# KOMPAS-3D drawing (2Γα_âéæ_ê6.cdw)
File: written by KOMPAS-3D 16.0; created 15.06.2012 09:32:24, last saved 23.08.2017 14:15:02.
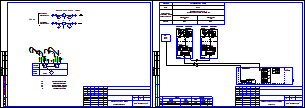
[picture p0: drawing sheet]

Sheets 1-2: A3, landscape

Title block, sheet 1: name: Руководство по эксплуатации; sheet number: 1; sheets: 27; organisation: ООО"Интелприбор"; sheet format: A3; stored path: W:\Users\smirnov_v\Desktop\шаблоны\4-х трубка\4-х трубка ГВС-max.cdw / D:\Проекты\Лыткарино\ул. Квартал 3А, д.25\710.74 РП.cdw; file name: 4-х трубка ГВС-max.cdw / 710.74 РП.cdw; cell 51: МО, Воскресенсикй р-н, п. Хорлово, ул. Интернациональная, д. 4; cell 320: Р
Title block, sheet 2: sheet number: 2

Views: Вид 2, Вид 3
Referenced files in C:\Program Files (x86)\ASCON\KOMPAS-3D V16\Sys\: spds.lcs, EngSys.lcs, GRAPHIC.LHS
Referenced files: graphic.tdp
Referenced files in W:\Users\smirnov_v\Desktop\шаблоны\4-х трубка\: 4-х трубка ГВС-max.cdw
Referenced files in D:\Проекты\Лыткарино\ул. Квартал 3А, д.25\: 710.74 РП.cdw
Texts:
  Смирнов В.С.
  УУ-3423
  GOST Common
  Normal
  List Paragraph
  heading 3
  для схемы
  txt
  Т0-элементы
  ВРУ
  Плата подключений
  СБ МКТС
  UP+
  UP-
  ИМП
  Лин
  Измерительный
  модуль М121
  Pt 100
  Преобразователь
  температуры
  давления
  каб.
  Начало
  трассы
  Трассы
  Марка
  Проложен
  Изм. модуль (Т3)
  Изм. модуль (Т4)
  ВРУ 220В, 50 Гц
  ИМ (Т1)
  FTP
  ПВС
  Конец
  Кол-во и
  сеч. жил
  Длина,
  Агрегат
  Системный блок  МКТС
  Среда
  Вода
  параметра и место
  отбора импульса
  Учет тепловой энергии и
  расхода горячей воды системы ГВС
  Подающий
  трубопровод
  ГВС
  Обратный
  ИМ1
  ИМ2
  приборы
  по месту
  шкаф
  учета
  UQIES
  УУГВС
  Функциональная схема
  Преобразователь расхода
  Термопреобразователь
  Преобразователь давления
  Преобразователь цифровой
  Системный блок МКТС
  Размеры, параметризация
  сит. план
  подача ГВС
  обратка ГВС
  хвс
  обратка
  POLYLINE_STYLE_0.25_RGB_0_0_0
  стены
  Основная (не является границей для штриховки)
  POLYLINE_STYLE_0.18_RGB_0_0_0
  ХВС
  зеленая
  Красная тонкая
  арматура
  Подача
  Скрытая линия
  Ось Z
  Ось Y
  Ось X
  Образующая трубопровода (проектируемого)
  Трубопровод толщиной 0.6мм (одна линия)
  Трубопровод толщиной 1.2мм (одна линия)
  Трубопровод толщиной 1.0мм (одна линия)
  Трубопровод толщиной 0.8мм (одна линия)
  Трубопровод существующий (одна линия)
  Трубопровод невидимый (одна линия)
  Трубопровод демонтируемый (одна линия)
  Осевая трубопровода
  Осевая трубопровода (демонтируемого)
  Образующая трубопровода (существующего)
  Образующая трубопровода (невидимого)
  Изолированный трубопровод проектируемый (одна линия)
  Изолированный трубопровод существующий (одна линия)
  Образующая изоляции
  Изоляция
  Изолированный трубопровод невидимый (одна линия)
  Штрих пвс 075
  штрих пвс 2,5
  существующее оборудование
  Существующее оборудование
  K5LT_BASIC_RGB_0_0_255_THICK_0.53
  POLYLINE_STYLE_1.51_RGB_0_0_255
  POLYLINE_STYLE_0.50_RGB_128_128_128
  K5LT_AXLED_RGB_255_128_0_SC_1_THICK_0.18
  ACAD_ISO04W100_RGB_0_0_0_SC_1_THICK_0.18
  тонкая черная
  тонкая красная
  тонкая синяя
  тонкая оранж
  красн штрих
  пломбировка
  Провода
  синий штрих
  Стили документа
  G2co
  расход вторичной воды объемный
  расход вторичной воды объемный при 70гр
  Gco
  расход теплоносителя массовый
  расход теплоносит объемн подающ
  расход теплоносит объемн обр
  Лапир
  Ghvs
  Im1
  Im2
  Im3
  Im4
  Im5
  Khvs
  норматив ХВС
  число подъездов
  число этажей
  Nkv
  число квартир
  тепловая нагрузка на отопление
  сумма Q
  Qgvs
  тепловая нагрузка ГВС
  тепловая нагрузка на циркуляцию ГВС
  иммитовставка или под манометр
  ro1
  ro2
  ro3
  ro4
  верх предел темп граф
  нижн предел темп граф
  темп подачи ГВС
  темп обр ГВС
  темр хол воды
  vzdh
  Kchn
  Ktp
  Knp
  tnv
  Vклап
  KLP
  RPD
  RDS
  PUMP
  ro5
  beta
  tnv98
  Shifr
  Переход ГОСТ 17378-2001
  Переход
  ГОСТ
  Сталь 09Г2С ГОСТ 19281-89
  Втулка 20x50
  Лит-Масса-Масштаб
  Материал-Предприятие
  Title Specification
  Body Specification ( left align )
  Body Specificaton ( centered )
  Поз.
  Кол.
  Приме-
  чание
  Таблица спецификации
  Засыпка
  Штрих3
  Штрих2
  Штрих1
  Песок
  Штр0.5пр7
  Штр0.5пр12
  Штр0.3пр10
  Штр1.4пр21.21
  Штр1пр15
  Штр2.12пр35
  Штр1.5пр25
  Штр2.82пр42.42
  Штр2пр30
  SACNCR_ISO 1
  Электрощитовая
  Пр-1
  Ок-1
  Обозначение стандарта
  Типоразмер
  Пояснительная записка
  автоматизации
  Рабочие чертежи основного комплекта. ГОСТ Р 21.1101-2009 Ф3
  Стадия
  Лист
  Листов
  Изм.
  Кол.уч.
  №док.
  Подп.
  Дата
  Разраб.
  Пров.
  Т.контр.
  Н.контр.
  Утв.
  Изменение
  Номер документа
  Подпись
  Наименование объекта строительства, в состав которого входит здание, наим. микр
  Наименование здания (сооружения)
  Порядковый номер листа
  Количество листов в документе
  Наименование изображения
  Индекс предприятия, выпускающего документ
  Инв. № подл.
  Подп. и дата
  Взам. инв. №
  Инвентарный номер подлинника
  Подпись принявшего подлинник на хранение
  Инвентарный номер подлинника, взамен которого выпущен данный подлинник
  Согласовано
  Формат листа
  Согласование
  03 Рабочие чертежи основного комплекта. ГОСТ Р 21.1101-2009 Ф3
  Схема соединений внешних
  проводок
Dimensions and other numbers on the sheet: 220В; 50Гц; 1; 2; 3; 6; 5; 4; 4-20; 2x2x0,52; 3х0,75; 50; 9; 7; 8; 0; 0,0; 0,0000; 1,2; 3,4; 5,6; 7,8; 10; 09Г2С; 20; 27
